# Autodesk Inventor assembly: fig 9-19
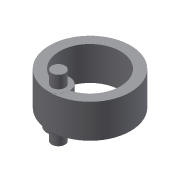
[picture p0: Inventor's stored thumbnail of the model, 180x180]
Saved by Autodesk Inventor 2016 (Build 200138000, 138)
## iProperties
Shininess: 64.0
Length Units: 11269
Angle Units: 11279
Time Units: 11290
Mass Units: 11283
Length Display Precision: 3
Angle Display Precision: 2
Created: 2002-01
Part Number: fig 9-19
Document SubType Name: Assembly
Designer: ***
Density: 0.0
Volumn: 0.0
Area: 0.0
PropertySet Name: Model Information
Control State: 0
Master: False
Checked Out: False
Author: ***
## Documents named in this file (3)
- D:\KAVITA\Autodesk Inventor_ 2016 Project_Kavita\Inventor_Part Files\Inventor_2016_Part\c09_Inv_2016\c09_inv_2016_prt\fig 9-19.iam
- D:\KAVITA\Autodesk Inventor_ 2016 Project_Kavita\Inventor_Part Files\Inventor_2016_Part\c09_Inv_2016\c09_inv_2016_prt\Part8.ipt
- D:\KAVITA\Autodesk Inventor_ 2016 Project_Kavita\Inventor_Part Files\Inventor_2016_Part\c09_Inv_2016\c09_inv_2016_prt\Part9.ipt
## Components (2 placed, 2 different names)
1. Part8:1 — Flush:1
2. Part9:1 — Flush:1
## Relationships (1: Flush 1)
- Flush:1: Part8:1 ↔ Part9:1
